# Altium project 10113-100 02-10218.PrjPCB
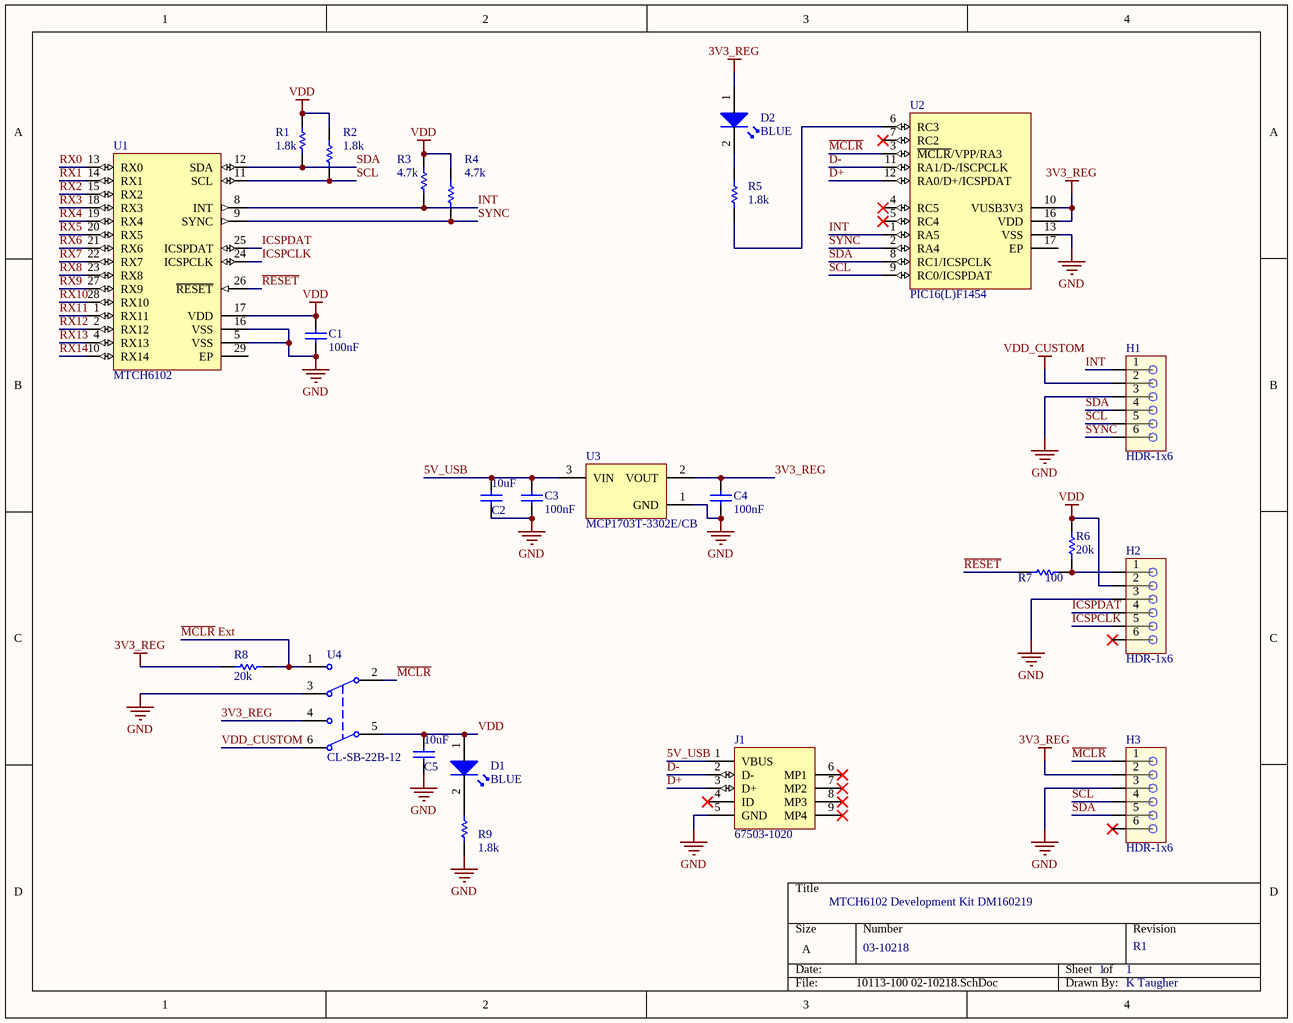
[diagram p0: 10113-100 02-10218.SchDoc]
1 sheet, 24 parts. Net scope: global (net labels, ports and power ports of the same name join across sheets).
Board file: 10113-100 02-10218.PcbDoc

## Sheet 10113-100 02-10218.SchDoc: MTCH6102 Development Kit DM160219
size A; DrawnBy: Andrew Voris; DocumentNumber: 03-10218; Revision: R1; SheetNumber: 1; SheetTotal: 1

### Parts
C1  value 100nF  [CAPC0402(1005)60_L]  (hidden comment: CAP 100nF 25V 0402(1005))
C2  10uF  [CAPC0603(1608)100_N]
C3  value 100nF  [CAPC0402(1005)60_L]  (hidden comment: CAP 100nF 25V 0402(1005))
C4  value 100nF  [CAPC0402(1005)60_L]  (hidden comment: CAP 100nF 25V 0402(1005))
C5  10uF  [CAPC0603(1608)100_N]
D1  BLUE  [LED_SMT-0603]
D2  BLUE  [LED_SMT-0603]
H1  HDR-1x6  [HDR-1x6_SMT]
H2  HDR-1x6  [HDR-1x6_TH-0.05"]
H3  HDR-1x6  [HDR-1x6_TH-0.05"]
J1  67503-1020  [MOLX-67503-1020_V]
R1  1.8k  [RESC0603(1608)_M]
R2  1.8k  [RESC0603(1608)_M]
R3  4.7k  [RESC0603(1608)_M]
R4  4.7k  [RESC0603(1608)_M]
R5  1.8k  [RESC0603(1608)_M]
R6  20k  [RESC0603(1608)_M]
R7  100  [RESC0603(1608)_M]
R8  20k  [RESC0603(1608)_M]
R9  1.8k  [RESC0603(1608)_M]
U1  MTCH6102  [MTCH6102_I/MV]
U2  PIC16(L)F1454  [PIC16LF1454_I/ML]
U3  MCP1703T-3302E/CB  [SOT-23A-CB3_L]
U4  CL-SB-22B-12  [CL-SB-22B-12]

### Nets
3V3_REG: C4.2 D2.1 H3.2 R8.1 U2.10(VUSB3V3) U2.16(VDD) U3.2(VOUT) U4.4
GND: C1.2 C2.1 C3.1 C4.1 C5.1 H1.3 H2.3 H3.3 J1.5(GND) R9.1 U1.5(VSS) U1.16(VSS) U2.13(VSS) U3.1(GND) U4.3
VDD: C1.1 C5.2 D1.1 H2.2 R1.2 R2.2 R3.2 R4.2 R6.1 U1.17(VDD) U4.5
VDD_CUSTOM: H1.2 U4.6
5V_USB: C2.2 C3.2 J1.1(VBUS) U3.3(VIN)
~{MCLR}: H3.1 U2.3(~{MCLR}/VPP/RA3) U4.2
~{MCLR} Ext: R8.2 U4.1
D+: J1.3(D+) U2.12(RA0/D+/ICSPDAT)
D-: J1.2(D-) U2.11(RA1/D-/ISCPCLK)
ICSPCLK: H2.5 U1.24(ICSPCLK)
ICSPDAT: H2.4 U1.25(ICSPDAT)
INT: H1.1 R3.1 U1.8(INT) U2.1(RA5)
~{RESET}: R7.2 U1.26(~{RESET})
RX0: U1.13(RX0)
RX1: U1.14(RX1)
RX2: U1.15(RX2)
RX3: U1.18(RX3)
RX4: U1.19(RX4)
RX5: U1.20(RX5)
RX6: U1.21(RX6)
RX7: U1.22(RX7)
RX8: U1.23(RX8)
RX9: U1.27(RX9)
RX10: U1.28(RX10)
RX11: U1.1(RX11)
RX12: U1.2(RX12)
RX13: U1.4(RX13)
RX14: U1.10(RX14)
SCL: H1.5 H3.4 R2.1 U1.11(SCL) U2.9(RC0/ICSPDAT)
SDA: H1.4 H3.5 R1.1 U1.12(SDA) U2.8(RC1/ICSPCLK)
SYNC: H1.6 R4.1 U1.9(SYNC) U2.2(RA4)
NetD1_2: D1.2 R9.2
NetD2_2: D2.2 R5.2
NetH2_1: H2.1 R6.2 R7.1
NetR5_1: R5.1 U2.6(RC3)

Not connected (* = marked no-connect by the designer): H2 6*; H3 6*; J1 4(ID)* 6(MP1)* 7(MP2)* 8(MP3)* 9(MP4)*; U1 29(EP); U2 4(RC5)* 5(RC4)* 7(RC2)* 17(EP)

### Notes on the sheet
- K Taugher

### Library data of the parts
C1 C3 C4 = CMP-1034-02073-1: CAP 100nF 25V ±20% 0402 (1005 Metric) Thickness 0.6mm SMD; Case-EIA: 0402; Case-Metric: 1005
C2 C5 = CMP-1035-02799-1: CAP 10uF 10V ±10% 0603 (1608 Metric) Thickness 1mm SMD; Case-Metric: 1608; Case-EIA: 0603
D1 D2 = LTST-C191KGKT: Discrete LED
H1-H3 = HDR-1x6_SMT: 0.1" pitch 6-pin SMT male header
J1 = CMP-0411-00002-1: USB, MINI, SMD, RA KME04-USBMU03A01; Manufacturer: Molex
R1-R9 = CMP-1012-00080-1: 1K8 0.1W 5% 0603 (1608 Metric)  SMD; Case-Metric: 1608; Case-EIA: 0603; Value: 1800.00 Ohm
U1 = MTCH6102: MTCH6102 Single Touch Controller
U2 = PIC16(L)F1454: PIC16(L)F1454 General Purpose Microcontroller
U3 = CMP-0136-00759-1: 250 mA, 16V, Low Quiescent Current LDO Regulator, 3-Pin SOT-23A, Extended Temperature, Tape and Reel
U4 = CL-SB-22B-12: Copal DPDT Slide Switch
